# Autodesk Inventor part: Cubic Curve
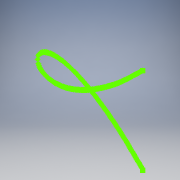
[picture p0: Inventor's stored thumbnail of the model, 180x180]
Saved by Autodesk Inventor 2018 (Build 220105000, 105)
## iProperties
Created: 2008-02
Part Number: Cubic Curve
Document SubType Name: Modeling
Designer: Autodesk, Inc.
Density: 1 g/cm^3
Material: Generic
Appearance: Default
Author: Autodesk, Inc.
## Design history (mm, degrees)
sketch "Sketch1"
  geometry: 301 further points
  constraints: 301 other
